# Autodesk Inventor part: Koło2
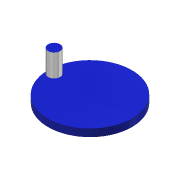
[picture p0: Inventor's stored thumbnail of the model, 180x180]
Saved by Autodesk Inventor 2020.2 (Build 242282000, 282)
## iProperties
Created: 2005-10
Part Number: Koło2
Document SubType Name: Modeling
Designer: F.Stasiak
Density: 1 g/cm^3
Material: Ogólny
Appearance: Niebieska — farba ścienna — lśniąca
Manager: www.cadconsulting.pl
Company: Fabian Stasiak CAD Consulting
Author: F.Stasiak
Subject: Zbiór ćwiczeń. Autodesk Inventor 2020. Kurs podstawowy
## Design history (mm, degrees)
sketch "Szkic1"
  geometry: C1 r 28 at (0, 0); 1 further point
  constraints: 1 centre point, 1 coincident
  dimensions: "d0" = 56 diameter of C1
extrude "Wyciągnięcie proste1" new body sketch "Szkic1" distance "d1" = 5; taper "d2" = 0 deg
sketch "Szkic2"
  geometry: C1 r 28 at (0, 0) reference; C2 r 4 at (-24, 0)
  constraints: 1 centre point, 1 tangent
  dimensions: "d3" = 8 diameter of C2
extrude "Wyciągnięcie proste2" join sketch "Szkic2" distance "d4" = 15; taper "d5" = 0 deg
sketch "Szkic3"
  geometry: C1 r 10 at (0, 0); 2 further points
  constraints: 1 centre point, 1 coincident, 1 horizontal alignment
  dimensions: "d6" = 20 diameter of C1
extrude "Wyciągnięcie proste3" join sketch "Szkic3" distance "d7" = 10; taper "d8" = 0 deg
node "Bryła1"
node "Korpusy bryłowe"
node "Korpusy powierzchniowe"
